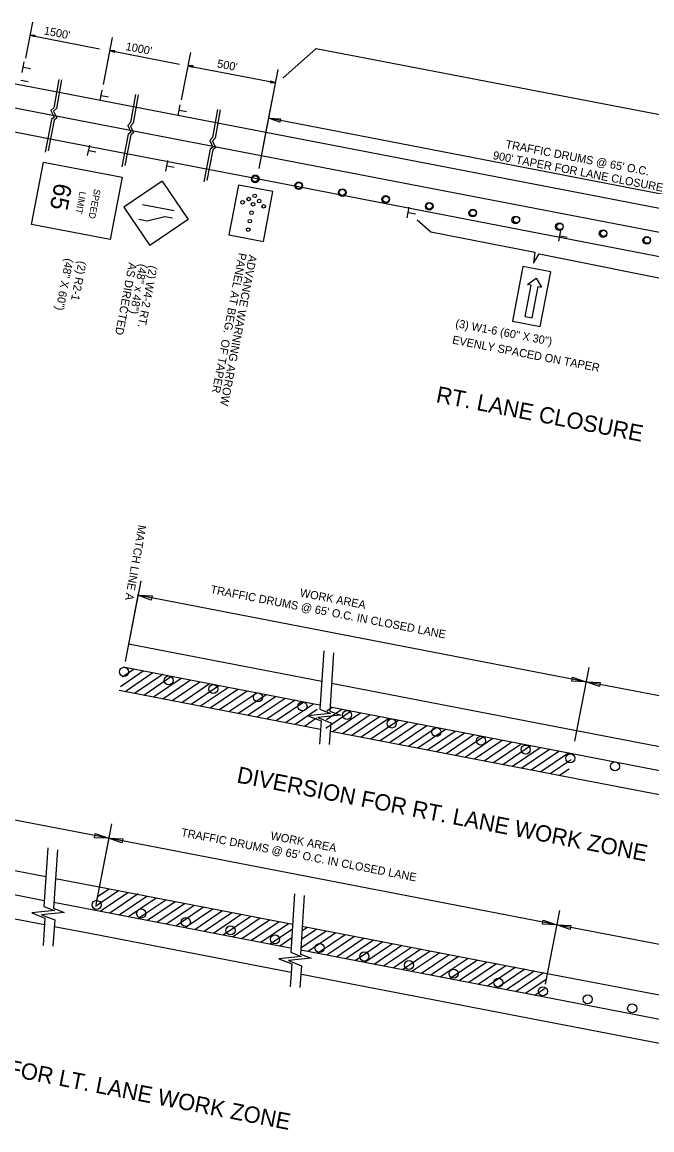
# Model space of a CAD drawing. Extents: x 606969 to 609391, y 416008 to 419486.
# Drawn here: x 607029.4 to 607075.7, y 419395.6 to 419477 of the extents above; entities that cross this region are included whole.
import ezdxf

# ---------------------------------------------------------------- set-up
doc = ezdxf.new("R2010")
doc.units = 0
doc.layers.add('Default', color=7, linetype='Continuous')

msp = doc.modelspace()

# ---------------------------------------------------------------- linework, layer by layer
at = {"layer": 'Default'}
for p, q in [((607030.152, 419477.006), (607029.643, 419474.37)), ((607029.967, 419476.045), (607035.091, 419475.055)), ((607030.324, 419475.918), (607029.967, 419476.045)), ((607030.345, 419476.029), (607029.967, 419476.045)), ((607030.326, 419475.927), (607030.028, 419476.033)), ((607030.344, 419476.019), (607030.028, 419476.033)), ((607030.342, 419476.01), (607030.091, 419476.02)), ((607030.328, 419475.937), (607030.091, 419476.02)), ((607030.329, 419475.946), (607030.153, 419476.009)), ((607030.34, 419476.001), (607030.153, 419476.009)), ((607030.338, 419475.991), (607030.215, 419475.997)), ((607030.331, 419475.956), (607030.215, 419475.997)), ((607030.336, 419475.982), (607030.277, 419475.985)), ((607030.333, 419475.965), (607030.277, 419475.985)), ((607030.324, 419475.918), (607030.345, 419476.029)), ((607036.013, 419475.875), (607035.346, 419472.417)), ((607035.828, 419474.913), (607040.952, 419473.924)), ((607036.185, 419474.787), (607035.828, 419474.913)), ((607036.206, 419474.897), (607035.828, 419474.913)), ((607036.187, 419474.796), (607035.889, 419474.901)), ((607036.205, 419474.888), (607035.889, 419474.901)), ((607036.203, 419474.879), (607035.952, 419474.889)), ((607036.189, 419474.805), (607035.952, 419474.889)), ((607036.19, 419474.815), (607036.014, 419474.877)), ((607036.201, 419474.87), (607036.014, 419474.877)), ((607036.199, 419474.86), (607036.076, 419474.865)), ((607036.192, 419474.824), (607036.076, 419474.865)), ((607036.197, 419474.851), (607036.138, 419474.853)), ((607036.194, 419474.833), (607036.138, 419474.853)), ((607036.185, 419474.787), (607036.206, 419474.897)), ((607041.758, 419474.766), (607041.091, 419471.308)), ((607029.402, 419473.31), (607029.55, 419474.078)), ((607029.487, 419473.69), (607030.011, 419473.588)), ((607041.573, 419473.804), (607048.001, 419472.563)), ((607041.93, 419473.678), (607041.573, 419473.804)), ((607041.952, 419473.788), (607041.573, 419473.804)), ((607041.932, 419473.687), (607041.634, 419473.792)), ((607041.95, 419473.779), (607041.634, 419473.792)), ((607041.948, 419473.77), (607041.698, 419473.78)), ((607041.934, 419473.696), (607041.698, 419473.78)), ((607041.936, 419473.706), (607041.759, 419473.768)), ((607041.946, 419473.761), (607041.759, 419473.768)), ((607041.944, 419473.751), (607041.821, 419473.756)), ((607041.938, 419473.715), (607041.821, 419473.756)), ((607041.943, 419473.742), (607041.883, 419473.744)), ((607041.939, 419473.724), (607041.883, 419473.744)), ((607041.93, 419473.678), (607041.952, 419473.788)), ((607023.092, 419473.591), (607031.596, 419471.95)), ((607048.187, 419473.525), (607046.782, 419466.245)), ((607029.302, 419472.742), (607029.826, 419472.641)), ((607047.644, 419472.69), (607047.622, 419472.579)), ((607047.622, 419472.579), (607048.001, 419472.563)), ((607047.624, 419472.588), (607047.94, 419472.575)), ((607047.626, 419472.598), (607047.877, 419472.587)), ((607047.628, 419472.607), (607047.815, 419472.599)), ((607047.63, 419472.616), (607047.753, 419472.611)), ((607047.631, 419472.626), (607047.691, 419472.623)), ((607047.635, 419472.643), (607047.691, 419472.623)), ((607047.637, 419472.652), (607047.753, 419472.611)), ((607047.638, 419472.662), (607047.815, 419472.599)), ((607047.64, 419472.671), (607047.877, 419472.587)), ((607047.642, 419472.68), (607047.94, 419472.575)), ((607047.644, 419472.69), (607048.001, 419472.563)), ((607022.763, 419471.884), (607031.266, 419470.243)), ((607031.596, 419471.95), (607047.298, 419468.919)), ((607035.119, 419471.244), (607035.268, 419472.012)), ((607035.204, 419471.624), (607035.729, 419471.523)), ((607047.754, 419471.283), (607047.087, 419467.826)), ((607040.869, 419470.156), (607041.017, 419470.924)), ((607040.953, 419470.536), (607041.478, 419470.434)), ((607022.433, 419470.177), (607031.837, 419468.362)), ((607031.266, 419470.243), (607046.968, 419467.212)), ((607091.877, 419461.373), (607047.495, 419469.94)), ((607047.495, 419469.94), (607048.373, 419469.903)), ((607048.324, 419469.647), (607047.495, 419469.94)), ((607048.373, 419469.903), (607048.324, 419469.647)), ((607047.298, 419468.919), (607117.284, 419455.409)), ((607030.937, 419468.536), (607046.639, 419465.505)), ((607034.209, 419467.194), (607034.357, 419467.962)), ((607034.294, 419467.574), (607034.818, 419467.473)), ((607046.968, 419467.212), (607116.955, 419453.702)), ((607039.95, 419466.065), (607040.098, 419466.833)), ((607040.035, 419466.445), (607040.559, 419466.343)), ((607039.697, 419465.313), (607036.874, 419463.404)), ((607039.697, 419465.313), (607041.606, 419462.491)), ((607046.639, 419465.505), (607116.625, 419451.995)), ((607036.874, 419463.404), (607038.784, 419460.582)), ((607038.232, 419463.614), (607040.559, 419463.165)), ((607057.698, 419462.635), (607057.846, 419463.403)), ((607037.969, 419462.52), (607038.571, 419462.404)), ((607038.571, 419462.404), (607039.88, 419462.724)), ((607041.606, 419462.491), (607038.784, 419460.582)), ((607039.88, 419462.724), (607040.453, 419462.613)), ((607057.783, 419463.014), (607058.307, 419462.913)), ((607068.845, 419460.917), (607068.994, 419461.685)), ((607068.93, 419461.297), (607069.455, 419461.196)), ((607066.357, 419455.383), (607066.799, 419457.671)), ((607066.544, 419457.721), (607067.162, 419458.181)), ((607066.799, 419457.671), (607066.544, 419457.721)), ((607066.867, 419455.285), (607067.309, 419457.573)), ((607067.162, 419458.181), (607067.564, 419457.524)), ((607067.309, 419457.573), (607067.564, 419457.524)), ((607066.357, 419455.383), (607066.867, 419455.285)), ((607038.109, 419435.94), (607036.966, 419430.014)), ((607037.933, 419435.025), (607036.966, 419430.014)), ((607037.933, 419435.025), (607036.966, 419430.014)), ((607037.933, 419435.025), (607036.966, 419430.014)), ((607070.832, 419428.525), (607037.905, 419434.881)), ((607037.905, 419434.881), (607038.946, 419434.837)), ((607038.887, 419434.534), (607037.905, 419434.881)), ((607038.946, 419434.837), (607038.887, 419434.534)), ((607037.215, 419431.309), (607051.431, 419428.565)), ((607036.614, 419428.189), (607038.3, 419429.33)), ((607036.748, 419428.883), (607037.605, 419429.464)), ((607036.817, 419429.616), (607051.243, 419426.831)), ((607036.958, 419427.818), (607038.994, 419429.196)), ((607037.652, 419427.684), (607039.753, 419429.105)), ((607038.346, 419427.55), (607040.382, 419428.927)), ((607071.036, 419429.584), (607069.987, 419424.149)), ((607039.041, 419427.416), (607041.077, 419428.793)), ((607039.735, 419427.282), (607041.771, 419428.659)), ((607040.429, 419427.148), (607042.465, 419428.525)), ((607041.123, 419427.014), (607043.16, 419428.391)), ((607041.818, 419426.88), (607043.854, 419428.257)), ((607042.512, 419426.746), (607044.548, 419428.123)), ((607052.136, 419428.429), (607070.142, 419424.953)), ((607069.791, 419428.568), (607069.849, 419428.872)), ((607070.832, 419428.525), (607069.791, 419428.568)), ((607069.849, 419428.872), (607070.832, 419428.525)), ((607101.182, 419422.666), (607070.832, 419428.525)), ((607070.832, 419428.525), (607071.873, 419428.481)), ((607071.814, 419428.178), (607070.832, 419428.525)), ((607071.873, 419428.481), (607071.814, 419428.178)), ((607036.535, 419427.9), (607051.323, 419425.045)), ((607043.206, 419426.612), (607045.243, 419427.989)), ((607043.901, 419426.478), (607045.937, 419427.855)), ((607044.595, 419426.344), (607046.631, 419427.721)), ((607045.289, 419426.21), (607047.325, 419427.587)), ((607045.983, 419426.076), (607048.02, 419427.453)), ((607046.678, 419425.942), (607048.714, 419427.319)), ((607047.372, 419425.808), (607049.408, 419427.185)), ((607048.066, 419425.674), (607050.103, 419427.051)), ((607048.761, 419425.54), (607050.797, 419426.917)), ((607049.455, 419425.406), (607051.081, 419426.506)), ((607051.753, 419425.753), (607052.88, 419426.515)), ((607051.798, 419426.387), (607052.185, 419426.649)), ((607052.02, 419426.681), (607069.813, 419423.246)), ((607050.149, 419425.272), (607051.036, 419425.872)), ((607051.708, 419425.119), (607053.574, 419426.381)), ((607052.232, 419424.87), (607054.268, 419426.247)), ((607052.926, 419424.736), (607054.963, 419426.113)), ((607053.621, 419424.602), (607055.657, 419425.979)), ((607054.315, 419424.468), (607056.351, 419425.845)), ((607055.009, 419424.334), (607057.045, 419425.711)), ((607052.074, 419424.9), (607069.484, 419421.539)), ((607055.704, 419424.2), (607057.74, 419425.577)), ((607056.398, 419424.066), (607058.434, 419425.443)), ((607057.092, 419423.932), (607059.128, 419425.309)), ((607057.786, 419423.798), (607059.823, 419425.175)), ((607058.481, 419423.664), (607060.517, 419425.041)), ((607059.175, 419423.53), (607061.211, 419424.907)), ((607070.142, 419424.953), (607103.908, 419418.435)), ((607059.869, 419423.396), (607061.905, 419424.773)), ((607060.564, 419423.262), (607062.6, 419424.639)), ((607061.258, 419423.128), (607063.294, 419424.505)), ((607061.952, 419422.994), (607063.988, 419424.371)), ((607062.646, 419422.859), (607064.683, 419424.237)), ((607063.341, 419422.725), (607065.377, 419424.103)), ((607064.035, 419422.591), (607066.071, 419423.969)), ((607064.729, 419422.457), (607066.766, 419423.835)), ((607065.424, 419422.323), (607067.46, 419423.701)), ((607066.118, 419422.189), (607068.154, 419423.567)), ((607066.812, 419422.055), (607068.848, 419423.433)), ((607067.506, 419421.921), (607069.543, 419423.299)), ((607069.813, 419423.246), (607103.579, 419416.729)), ((607035.75, 419417.024), (607005.4, 419422.882)), ((607068.201, 419421.787), (607069.732, 419422.823)), ((607068.895, 419421.653), (607069.598, 419422.129)), ((607069.484, 419421.539), (607103.249, 419415.022)), ((607004.73, 419419.307), (607031.136, 419414.21)), ((607004.312, 419417.617), (607031.02, 419412.462)), ((607035.955, 419418.083), (607034.811, 419412.157)), ((607034.709, 419417.067), (607034.768, 419417.371)), ((607035.75, 419417.024), (607034.709, 419417.067)), ((607034.768, 419417.371), (607035.75, 419417.024)), ((607035.778, 419417.168), (607034.811, 419412.157)), ((607035.778, 419417.168), (607034.811, 419412.157)), ((607035.778, 419417.168), (607034.811, 419412.157)), ((607068.677, 419410.668), (607035.75, 419417.024)), ((607035.75, 419417.024), (607036.791, 419416.98)), ((607036.733, 419416.677), (607035.75, 419417.024)), ((607036.791, 419416.98), (607036.733, 419416.677)), ((607004.03, 419415.901), (607031.038, 419410.688)), ((607031.851, 419414.072), (607035.061, 419413.452)), ((607035.061, 419413.452), (607049.276, 419410.708)), ((607034.788, 419412.039), (607036.474, 419413.179)), ((607034.922, 419412.733), (607035.78, 419413.313)), ((607035.132, 419411.668), (607037.168, 419413.045)), ((607035.827, 419411.534), (607037.928, 419412.955)), ((607036.521, 419411.4), (607038.557, 419412.777)), ((607037.215, 419411.266), (607039.251, 419412.643)), ((607031.735, 419412.324), (607034.663, 419411.759)), ((607037.909, 419411.132), (607039.946, 419412.509)), ((607038.604, 419410.998), (607040.64, 419412.375)), ((607039.298, 419410.864), (607041.334, 419412.241)), ((607039.992, 419410.73), (607042.028, 419412.107)), ((607040.687, 419410.596), (607042.723, 419411.973)), ((607041.381, 419410.462), (607043.417, 419411.839)), ((607034.663, 419411.759), (607049.089, 419408.974)), ((607042.075, 419410.328), (607044.111, 419411.705)), ((607042.769, 419410.194), (607044.806, 419411.571)), ((607043.464, 419410.06), (607045.5, 419411.437)), ((607044.158, 419409.926), (607046.194, 419411.303)), ((607044.852, 419409.792), (607046.889, 419411.169)), ((607045.547, 419409.658), (607047.583, 419411.035)), ((607067.636, 419410.711), (607067.695, 419411.014)), ((607067.695, 419411.014), (607068.677, 419410.668)), ((607068.882, 419411.727), (607067.833, 419406.292)), ((607031.754, 419410.55), (607034.381, 419410.042)), ((607046.241, 419409.524), (607048.277, 419410.901)), ((607046.935, 419409.39), (607048.971, 419410.767)), ((607047.629, 419409.256), (607049.256, 419410.356)), ((607049.882, 419408.969), (607051.749, 419410.231)), ((607049.927, 419409.603), (607051.054, 419410.365)), ((607049.973, 419410.237), (607050.36, 419410.499)), ((607049.982, 419410.572), (607067.988, 419407.096)), ((607068.677, 419410.668), (607067.636, 419410.711)), ((607099.028, 419404.809), (607068.677, 419410.668)), ((607068.677, 419410.668), (607069.718, 419410.624)), ((607069.66, 419410.321), (607068.677, 419410.668)), ((607069.718, 419410.624), (607069.66, 419410.321)), ((607034.381, 419410.042), (607049.168, 419407.188)), ((607048.324, 419409.122), (607049.211, 419409.722)), ((607050.407, 419408.72), (607052.443, 419410.097)), ((607051.101, 419408.586), (607053.137, 419409.963)), ((607051.795, 419408.452), (607053.831, 419409.829)), ((607052.489, 419408.318), (607054.526, 419409.695)), ((607053.184, 419408.184), (607055.22, 419409.561)), ((607053.878, 419408.049), (607055.914, 419409.427)), ((607049.866, 419408.824), (607067.659, 419405.389)), ((607054.572, 419407.915), (607056.609, 419409.293)), ((607055.267, 419407.781), (607057.303, 419409.159)), ((607055.961, 419407.647), (607057.997, 419409.025)), ((607056.655, 419407.513), (607058.691, 419408.891)), ((607057.35, 419407.379), (607059.386, 419408.757)), ((607058.044, 419407.245), (607060.08, 419408.623)), ((607058.738, 419407.111), (607060.774, 419408.489)), ((607059.432, 419406.977), (607061.469, 419408.355)), ((607060.127, 419406.843), (607062.163, 419408.221)), ((607060.821, 419406.709), (607062.857, 419408.087)), ((607061.515, 419406.575), (607063.551, 419407.953)), ((607062.21, 419406.441), (607064.246, 419407.819)), ((607049.92, 419407.043), (607067.329, 419403.682)), ((607062.904, 419406.307), (607064.94, 419407.685)), ((607063.598, 419406.173), (607065.634, 419407.551)), ((607064.292, 419406.039), (607066.329, 419407.417)), ((607064.987, 419405.905), (607067.023, 419407.282)), ((607065.681, 419405.771), (607067.717, 419407.148)), ((607067.988, 419407.096), (607101.754, 419400.578)), ((607066.375, 419405.637), (607067.906, 419406.673)), ((607067.07, 419405.503), (607067.772, 419405.978)), ((607067.659, 419405.389), (607101.424, 419398.872)), ((607067.329, 419403.682), (607101.095, 419397.165))]:
    msp.add_line(p, q, dxfattribs=at)
for points in [[(607048.557, 419472.877), (607050.993, 419475.073), (607092.07, 419467.192), (607093.32, 419469.415), (607092.939, 419467.06), (607117.097, 419462.057), (607117.726, 419459.29)], [(607032.086, 419472.779), (607031.719, 419470.708), (607031.514, 419470.502), (607031.742, 419470.017), (607031.541, 419469.852), (607031.077, 419467.451)], [(607032.286, 419472.76), (607031.914, 419470.662), (607031.708, 419470.456), (607031.937, 419469.971), (607031.736, 419469.806), (607031.3, 419467.551)], [(607037.728, 419471.69), (607037.361, 419469.619), (607037.156, 419469.413), (607037.384, 419468.928), (607037.183, 419468.763), (607036.719, 419466.362)], [(607037.927, 419471.671), (607037.555, 419469.573), (607037.35, 419469.367), (607037.579, 419468.882), (607037.377, 419468.717), (607036.942, 419466.462)], [(607043.754, 419470.591), (607043.386, 419468.52), (607043.181, 419468.314), (607043.41, 419467.829), (607043.208, 419467.664), (607042.744, 419465.263)], [(607043.953, 419470.572), (607043.581, 419468.474), (607043.376, 419468.268), (607043.604, 419467.783), (607043.403, 419467.618), (607042.967, 419465.363)], [(607058.433, 419462.471), (607059.441, 419461.583), (607067.065, 419460.111), (607066.977, 419459.295), (607067.387, 419459.98), (607078.276, 419457.808), (607079.766, 419458.701)], [(607051.57, 419430.801), (607051.284, 419426.502), (607052.067, 419426.202), (607050.401, 419426.029), (607051.366, 419425.645), (607051.245, 419423.952)], [(607052.285, 419430.663), (607051.999, 419426.364), (607052.782, 419426.064), (607051.116, 419425.891), (607052.081, 419425.507), (607051.968, 419423.919)], [(607031.276, 419416.316), (607030.99, 419412.016), (607031.773, 419411.717), (607030.107, 419411.543), (607031.072, 419411.159), (607030.929, 419409.143)], [(607031.991, 419416.178), (607031.705, 419411.878), (607032.488, 419411.579), (607030.823, 419411.405), (607031.787, 419411.021), (607031.65, 419409.092)], [(607049.415, 419412.944), (607049.129, 419408.645), (607049.912, 419408.345), (607048.247, 419408.172), (607049.211, 419407.788), (607049.091, 419406.095)], [(607050.13, 419412.806), (607049.844, 419408.507), (607050.627, 419408.207), (607048.962, 419408.034), (607049.926, 419407.65), (607049.813, 419406.061)]]:
    msp.add_lwpolyline(points, dxfattribs=at)
for points in [[(607035.869, 419461.022), (607030.089, 419462.138), (607030.974, 419466.724), (607036.755, 419465.608)], [(607045.3, 419465.036), (607044.594, 419461.379), (607047.124, 419460.891), (607047.83, 419464.548)], [(607066.195, 419459.046), (607065.42, 419455.034), (607067.472, 419454.637), (607068.247, 419458.65)]]:
    msp.add_lwpolyline(points, close=True, dxfattribs=at)
for centre, radius in [((607046.528, 419465.489), 0.281), ((607046.515, 419465.496), 0.229), ((607046.527, 419465.493), 0.229), ((607049.724, 419464.985), 0.281), ((607049.727, 419464.992), 0.229), ((607052.92, 419464.481), 0.281), ((607052.927, 419464.491), 0.229), ((607045.593, 419463.767), 0.131), ((607046.041, 419464.003), 0.131), ((607046.488, 419464.238), 0.131), ((607046.815, 419463.853), 0.131), ((607056.116, 419463.977), 0.281), ((607056.127, 419463.991), 0.229), ((607046.248, 419462.996), 0.131), ((607046.368, 419463.617), 0.131), ((607047.143, 419463.468), 0.131), ((607059.312, 419463.473), 0.281), ((607059.327, 419463.49), 0.229), ((607062.508, 419462.969), 0.281), ((607062.527, 419462.989), 0.229), ((607046.128, 419462.376), 0.131), ((607065.66, 419462.472), 0.281), ((607065.727, 419462.488), 0.229), ((607046.009, 419461.755), 0.131), ((607068.873, 419461.971), 0.281), ((607068.926, 419461.987), 0.229), ((607072.086, 419461.469), 0.281), ((607072.126, 419461.486), 0.229), ((607075.299, 419460.967), 0.281), ((607075.326, 419460.985), 0.229), ((607036.875, 419429.256), 0.333), ((607040.156, 419428.623), 0.333), ((607043.437, 419427.99), 0.333), ((607046.721, 419427.377), 0.333), ((607049.997, 419426.723), 0.333), ((607053.276, 419426.079), 0.333), ((607056.559, 419425.461), 0.333), ((607059.84, 419424.828), 0.333), ((607063.12, 419424.195), 0.333), ((607066.398, 419423.546), 0.333), ((607069.676, 419422.901), 0.333), ((607072.966, 419422.315), 0.333), ((607034.862, 419412.13), 0.333), ((607038.143, 419411.496), 0.333), ((607041.423, 419410.864), 0.333), ((607044.707, 419410.25), 0.333), ((607047.984, 419409.597), 0.333), ((607051.262, 419408.953), 0.333), ((607054.546, 419408.335), 0.333), ((607057.826, 419407.702), 0.333), ((607061.107, 419407.069), 0.333), ((607064.384, 419406.42), 0.333), ((607067.663, 419405.775), 0.333), ((607070.952, 419405.189), 0.333), ((607074.227, 419404.524), 0.333)]:
    msp.add_circle(centre, radius, dxfattribs=at)

# ---------------------------------------------------------------- texts
for s, height, rotation, p in [("1500'", 0.6, 349.07451, (607030.955, 419476.111)), ("1000'", 0.6, 349.07451, (607036.967, 419474.959)), ("500'", 0.6, 349.07451, (607043.689, 419473.686)), ("TRAFFIC DRUMS @ 65' O.C.", 0.6, 349.07451, (607064.881, 419467.761)), ("900' TAPER FOR LANE CLOSURE", 0.6, 349.07451, (607063.954, 419466.949)), ('65', 1.3039, 259.07451, (607031.792, 419465.237)), ('SPEED', 0.4865, 259.07451, (607034.691, 419464.769)), ('LIMIT', 0.4865, 259.07451, (607033.633, 419464.593)), ('PANEL AT BEG.  OF TAPER', 0.6, 259.07451, (607045.317, 419460.089)), ('ADVANCE WARNING ARROW', 0.6, 259.07451, (607046.067, 419459.944)), ('(48" X 60")', 0.6, 259.07451, (607032.58, 419459.677)), ('(2) R2-1', 0.6, 259.07451, (607033.541, 419459.492)), ('AS DIRECTED ', 0.6, 259.07451, (607037.24, 419459.368)), ('(48" x 48")', 0.6, 259.07451, (607038.008, 419459.277)), ('(2) W4-2 RT.', 0.6, 259.07451, (607038.757, 419459.158)), ('(3) W1-6 (60" X 30")', 0.6, 349.08205, (607061.2, 419454.602)), ('EVENLY SPACED ON TAPER', 0.6, 349.08205, (607060.966, 419453.389)), ('RT. LANE CLOSURE', 1.2, 349.07451, (607059.757, 419449.085)), ('MATCH LINE A', 0.6, 259.88043, (607037.935, 419440.088)), ("TRAFFIC DRUMS @ 65' O.C. IN CLOSED LANE", 0.6, 349.07451, (607043.194, 419435.042)), ('WORK AREA', 0.6, 349.07451, (607049.771, 419434.799)), ('DIVERSION FOR RT. LANE WORK ZONE', 1.2, 349.07451, (607045.111, 419421.131)), ("TRAFFIC DRUMS @ 65' O.C. IN CLOSED LANE", 0.6, 349.07451, (607041.04, 419417.185)), ('WORK AREA', 0.6, 349.07451, (607047.617, 419416.942)), ('DIVERSION FOR LT. LANE WORK ZONE', 1.2, 349.07451, (607019.141, 419401.344))]:
    msp.add_text(s, height=height, rotation=rotation, dxfattribs=at).set_placement(p)

doc.saveas('drawing.dxf')
